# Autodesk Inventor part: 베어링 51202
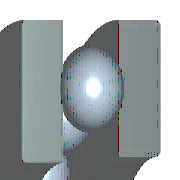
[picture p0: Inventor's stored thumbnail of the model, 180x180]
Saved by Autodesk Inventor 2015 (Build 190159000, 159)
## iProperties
Created: 2012-02
Part Number: 베어링 51202
Material: 강철, 연강
Description: 롤링 베어링 - 플랫 뒷면이 있는 스러스트 볼 베어링
Document SubType Name: Modeling
Standard: KS B 2022
Designer: mduedu
Standards Organization: KS
Language: ko-KR
Size Designation: 51202 - 15 x 32 x 12
Categories: <MemberInstance><Categories><Category DisplayName="샤프트 부품" InternalName="7f7aeb1f-a693-4053-b835-cee3144e0d98" Mnemonic="SHFT"><Category DisplayName="베어링" Inter
Density: 1 g/cm^3
Appearance: 진녹색
IsCustomPart: 1
Author: mduedu
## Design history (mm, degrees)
sketch "스케치1" dims "d3" = 5.28 (= 0.44 x KB)
  geometry: L1 (6, 9.61)-(6, 14.89); L2 (8.64, 12.25)-(3.36, 12.25); L3 (3.6, 16)-(0, 16); L4 (3.6, 7.5)-(0, 7.5); L5 (8.4, 13.35)-(8.4, 16); L6 (8.4, 16)-(12, 16); L7 (12, 16)-(12, 8.5); L8 (12, 8.5)-(8.4, 8.5); L9 (8.4, 8.5)-(8.4, 11.15); L10 (3.6, 16)-(3.6, 13.35); L11 (3.6, 11.15)-(3.6, 7.5); L12 (-1.8, 0)-(10.8, 0) reference; L13 (0, -0.022)-(0, 5.522) reference; 1 further point
  constraints: 22 end point, 5 perpendicular, 2 equal length, 2 midpoint, 2 parallel, 2 point on line, 1 collinear, 10 other
  dimensions: "d8" = 4.8 diameter of L11 L1 (= 0.4 x KB); "d11" = 15 diameter of L4 L12 (= WD); "d12" = 17 diameter of L8 L12 (= KAD1); "d13" = 32 diameter of L3 L12 (= KID1); "d14" = 32 diameter of L6 L12 (= BD); "d15" = 24.5 diameter of point (6, 12.25) L12 (= 0.5 x KID1 + 0.5 x KAD1); "d16" = 6 distance from line of point (6, 12.25) L13 (= 0.5 x KB); "d18" = 12 distance between parallel lines of L7 L13 (= KB)
revolve "본체" stored, may be unused: angle "d9" = 90 deg
revolve "볼" stored, may be unused: angle "d10" = 90 deg
pattern_circular "IDS_ARRAYBALL[SIMPL:T]" dims angle "d2" = 360 deg
body "Solid1"
fillet "모깎기1" dims "d4" = 0.6 (= KRS)
fillet "모깎기2" dims "d5" = 0.6 (= KRS)
other parameters: "WD" = 15 [user parameter; used in 2 equation terms], "KAD1" = 17 [user parameter; used in 3 equation terms], "KID1" = 32 [user parameter; used in 3 equation terms], "BD" = 32 [user parameter; used in 2 equation terms], "KB" = 12 [user parameter; used in 6 equation terms], "KRS" = 0.6 [user parameter; used in 2 equation terms], "d0" = 2.4 (= 0.2 x KB), "d6" = 0, "d7" = 0, "d19" = 0, "d41" = 0, "d42" = 0, "WR" = 7.5 (= 0.5 x WD) [user parameter], "BC" = 1.65e+07 [user parameter], "BBA" = 90 deg [user parameter], "BC0" = 2.7e+07 [user parameter], "BR" = 16 (= 0.5 x BD) [user parameter]
